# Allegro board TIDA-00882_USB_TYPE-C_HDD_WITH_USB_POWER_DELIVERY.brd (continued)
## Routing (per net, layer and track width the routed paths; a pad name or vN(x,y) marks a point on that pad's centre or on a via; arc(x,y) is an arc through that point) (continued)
GPIO7: length 4.6
  TOP w0.102: U9.D7 v1(30.73,63.62)
  TOP w0.241: R61.1 v1(33.13,65.74)
  BOTTOM w0.191: v1(30.73,63.62) 30.73,64.23 32.24,65.74 v1(33.13,65.74)
GPIO8: length 6.3
  TOP w0.102: v1(30.03,60.73) 30.23,60.93 U9.H6
  TOP w0.241: R65.1 v1(28.13,56.21)
  BOTTOM w0.191: v1(30.03,60.73) 28.13,58.83 v1(28.13,56.21)
GRST#: length 25.9
  TOP w0.191: v1(23.88,23.09) 24.79,23.09 R85.1 24.82,23.55 25.26,23.99 U13.20
  TOP w0.241: U6.4 v1(27.41,41.22)
  BOTTOM w0.191: v1(27.41,41.22) 29.57,39.06 29.57,31.14 28.18,29.74 27.45,29.74 23.88,26.18 v1(23.88,23.09)
HDD_LED#: length 15.8
  TOP w0.191: D1.1 v1(21.8,31.58)
  TOP w0.241: v1(26.6,41.22) 26.6,39.92 U6.2
  BOTTOM w0.191: v1(26.6,41.22) 24.37,41.22 22.71,39.56 22.71,38.24 21.05,36.59 21.05,32.33 v1(21.8,31.58)
HLD#: length 2.1
  TOP w0.241: R6.1 38.53,41.56 38.65,41.68 U7.7
HRESET: length 13.7
  TOP w0.102: v1(30.08,63.53) 30.23,63.37 U9.D6
  TOP w0.191: R52.1 v1(38.29,69.93)
  BOTTOM w0.191: v1(38.29,69.93) 38.29,67.62 37.54,66.87 32.51,66.87 30.11,64.47 30.11,64 30.08,63.98 v1(30.08,63.53)
HV_GATE1: length 5.9
  TOP w0.102: U8.C1 34.42,68.25 31.96,65.79 31.96,64.99 31.96,64.99 31.96,64.43 U9.B9
HV_GATE2: length 6.1
  TOP w0.102: U8.C2 34.15,69.36 34.15,68.88 34.17,68.85 34.17,68.29 31.73,65.85 U9.A9
I2C_ADDR: length 1.3
  TOP w0.102: U9.F1 27.39,62.2 27.29,62.31 R64.2
I2C_IRQ1Z: length 52.2
  TOP w0.102: U9.C1 27.29,63.7 27.08,63.5 26.37,63.5 v1(26.02,63.86)
  TOP w0.191: v1(18.73,58.39) 19.25,58.39 R91.2 ; R23.1 v1(29.09,31.6)
  BOTTOM w0.191: v1(26.02,63.86) 25.46,63.3 20.94,63.3 18.73,61.09 v1(18.73,58.39) 18.73,32.51 20.62,30.62 24.06,30.62 25.51,32.07 28.62,32.07 v1(29.09,31.6)
I2C_SCL: length 10.3
  TOP w0.191: J3.1 53.53,64.28 48.46,69.35 R50.1 R47.1
I2C_SCL1: length 84.5
  TOP w0.102: v1(28.71,63.09) 28.6,63.2 U9.D2
  TOP w0.191: R43.2 R50.2 v1(48.23,70.4) ; R22.1 v1(34.83,31.57)
  L3_SIG w0.191: v1(34.83,31.57) 34.83,34.14 42.98,42.29 42.98,48.01 41.79,49.2 39.73,49.2 34.76,54.18 25.89,54.18 24.54,55.52 v1(24.54,56.59) ; v1(48.23,70.4) 46.71,70.4 43.19,73.91 32.62,73.91 32.21,73.5 32.21,71.8 31.1,70.69 31.1,65.71 30.51,65.13 30.03,65.13 28.71,63.8 v1(28.71,63.09)
  BOTTOM w0.191: v1(24.54,56.59) 26.5,58.55 26.5,59.28 29.29,62.08 29.29,62.74 29.14,62.89 28.91,62.89 v1(28.71,63.09)
I2C_SCL2: length 27.3
  TOP w0.102: U9.B5 29.73,63.94 v1(29.6,63.83)
  TOP w0.191: R45.2 R47.2 v1(45.46,70.4)
  L3_SIG w0.191: v1(45.46,70.4) 42.42,73.44 33.08,73.44 32.65,73 32.65,71.4 31.58,70.33 31.58,65.33 30.4,64.15 29.92,64.15 v1(29.6,63.83)
I2C_SDA: length 11.1
  TOP w0.191: J3.3 56.98,64.26 56.98,61.57 56.57,61.16 52.59,61.16 51.9,61.85 R49.1 R48.1
I2C_SDA1: length 81.1
  TOP w0.102: v1(25.36,64.34) 25.64,64.06 25.64,63.7 26.13,63.2 U9.D1
  TOP w0.191: R21.1 v1(27.95,31.62) ; v1(48.2,62.45) R44.2 R49.2
  L4_PWR w0.191: v1(39.76,64.16) 39.73,64.14 39.73,63.7 39.35,63.32 37.07,63.32 35.21,65.18 33.09,65.18 32.55,64.64 30.22,64.64 29.63,65.23 29.27,65.23 29.24,65.25 26.78,65.25 26.72,65.24 26.26,65.24 v1(25.36,64.34)
  BOTTOM w0.191: v1(39.76,64.16) 42.43,64.16 43.29,63.3 47.35,63.3 v1(48.2,62.45) ; v1(27.95,31.62) 27.5,31.62 27.47,31.6 25.77,31.6 24.33,30.16 20.52,30.16 18.07,32.62 18.07,62.46 20.35,64.74 22.72,64.74 23.12,64.34 v1(25.36,64.34)
I2C_SDA2: length 30.7
  TOP w0.102: v1(29.85,65.65) 29.85,65.27 29.73,65.15 U9.A5
  TOP w0.191: v1(48.2,61.13) R46.2 R48.2
  BOTTOM w0.191: v1(29.85,65.65) 30,65.8 30,66.69 30.7,67.39 37.14,67.39 37.55,67.8 37.55,69.94 38.04,70.43 40.19,70.43 45.12,65.51 46.31,65.51 48.85,62.97 48.85,61.77 v1(48.2,61.13)
ILIM1: length 2.2
  TOP w0.191: R87.1 24.06,15.67 23.47,16.26 U14.7
JACK_DETECT: length 27
  TOP w0.191: R19.1 v1(32.52,31.65)
  TOP w0.241: U12.1 v1(40.44,49.88) 39.88,50.43 R27.1
  BOTTOM w0.191: v1(40.44,49.88) 39.89,49.33 39.89,45.14 37.52,42.77 33.87,42.77 32.27,41.17 32.27,38.91 33.42,37.76 33.42,32.55 v1(32.52,31.65)
LDO_1V8A: length 3.8
  TOP w0.102: U9.K1 27.34,60.2 25.43,58.29 C61.2
LDO_1V8D: length 2.2
  TOP w0.191: U9.A2 28.23,64.78 27.3,65.71 C58.2
LDO_3V3: length 15.1
  TOP w0.102: U9.G1 27.35,61.7 v1(27.21,61.57)
  TOP w0.191: v1(42.22,57.16) 42.21,57.18 R39.1 ; R91.1 v1(21.02,58.39) ; R44.1 v1(47.16,62.45) ; R46.1 v1(47.16,61.15)
  TOP w0.241: R45.1 v1(46.26,73.23) ; U12.6 v1(41.14,51.29) ; R43.1 v1(47.38,73.23) ; R56.2 v1(26.86,58.14) ; R36.1 v1(21.84,66.59) ; R35.1 v1(23.59,67.32) ; R57.2 v1(28.58,58.19) ; C59.2 v1(23.66,62.74)
  BOTTOM w0.191: v1(60.74,72.44) 61.23,71.95 R40.1 ; R38.1 v1(58.34,68.03) ; R41.1 v1(61.17,61.7) ; C62.2 v1(58.34,64.17) ; v1(60.76,65.86) 61.04,65.58 U10.8 ; R42.2 v1(65.74,71.42)
LDO_BMC: length 4.3
  TOP w0.102: U9.E1 25.95,62.7 24.57,64.08 C60.2
MR#: length 1.6
  TOP w0.191: U13.1 26.64,22.22 26.63,22.21 R84.2
PD_BUSPWRZ: length 12.7
  TOP w0.102: U9.F10 31.93,61.9 v1(31.76,61.9)
  TOP w0.191: R39.2 40.33,58.41 40.16,58.58 v1(40.16,59.03)
  BOTTOM w0.191: v1(40.16,59.03) 36.66,59.03 35.92,59.77 35.92,59.77 33.38,59.77 32.82,60.33 32.82,61.29 32.21,61.9 v1(31.76,61.9)
PD_MRESET: length 13.9
  TOP w0.102: U9.E11 v1(33.76,62.7)
  TOP w0.191: R37.1 v1(44.36,60.83)
  BOTTOM w0.191: v1(33.76,62.7) 34.81,63.75 36.79,63.75 37.5,63.04 40.34,63.04 42.55,60.83 v1(44.36,60.83)
PGOOD: length 20.5
  TOP w0.191: U11.3 v1(41.72,33.4) ; R79.1 v1(51.95,33.1) ; R74.2 v1(52.2,37.44)
  BOTTOM w0.191: v1(51.95,33.1) 51.95,34.32 51.37,34.9 51.37,36.6 v1(52.2,37.44) 49.16,37.44 46.87,35.15 43.85,35.15 43.49,34.8 43.49,33.99 42.91,33.4 v1(41.72,33.4)
PMIC_5V: length 8.6
  TOP w0.191: v1(30.06,25.07) 29.78,24.79 U13.8 ; U13.3 27.44,22.83 v1(27.69,22.58) 27.84,22.73 U13.4 ; U13.18 25.41,24.79 v1(25.18,24.56) 25.35,24.39 U13.19 ; U14.9 23.47,17.26 24.2,18 C78.1 v1(24.2,19.24) ; R84.1 v1(25.88,20.66) ; U13.10 v1(28.94,26.01)
  vias: v1(25.74,26.97) v1(26.25,26.97)
POL: length 12.3
  TOP w0.191: R26.1 42.78,57.76 v1(42.78,57.53) ; U1.9 47.88,53.65 v1(46.68,52.45)
  L3_SIG w0.191: v1(47.15,56.21) 47.15,53.92 46.68,53.45 v1(46.68,52.45)
  L4_PWR w0.191: v1(47.15,56.21) 46.6,56.76 43.21,56.76 42.86,57.12 42.86,57.46 v1(42.78,57.53)
R_OSC: length 8.1
  TOP w0.102: U9.G2 27.95,61.99 26.77,61.99 26.62,61.84 25.39,61.84 25.08,62.15 25.08,63.17 24.84,63.41 R32.1
REF1: length 0.6
  TOP w0.241: U12.5 U12.4
RF: length 7.9
  TOP w0.191: R77.2 48,35.12 v1(47.97,35.09) U11.22 ; R73.2 v1(51.9,30.84)
  BOTTOM w0.191: v1(47.97,35.09) 48.29,34.77 48.29,34.44 v1(51.9,30.84)
SATA_5V:
  vias: v1(30.23,3.3) v1(30.23,2.67) v1(30.87,3.3) v1(30.87,2.67) v1(31.5,3.3) v1(31.5,2.67)
SATA_EN: length 40.1
  TOP w0.191: R86.1 R83.1 18.68,15.1 18.68,15.42 19.02,15.76 U14.5 v1(19.84,15.11)
  TOP w0.241: U6.22 v1(32.16,43.11)
  BOTTOM w0.191: v1(19.84,15.11) 19.84,17.65 20.61,18.41 20.61,20.95 21.52,21.87 24.11,21.87 26.22,23.98 26.22,24.71 29.26,27.75 29.26,30.11 31.53,32.38 31.53,37.87 30.95,38.46 30.95,42.42 31.63,43.11 v1(32.16,43.11)
SATARXM: length 46.1
  TOP w0.127: C12.2 12.53,4.67 12.6,4.75 12.6,6.63 13.66,7.69 13.66,35.32 21.4,43.05 21.64,43.05 23.88,43.05 23.93,43.11 U6.59
SATARXP: length 46.1
  TOP w0.127: C13.2 13.34,4.23 12.9,4.67 12.9,6.52 13.96,7.57 13.96,35.2 21.52,42.76 24.15,42.76 24.2,42.71 U6.60
SATATXM: length 49.3
  TOP w0.127: U6.56 24.22,44.31 24.17,44.25 20.77,44.25 12.49,35.98 12.49,10.26 8.81,6.57 8.81,4.76 8.72,4.67 C11.2
SATATXP: length 49.3
  TOP w0.127: C14.2 9.5,4.23 9.1,4.62 9.1,6.45 12.79,10.14 12.79,35.86 20.89,43.96 23.88,43.96 23.93,43.91 U6.57
SPI_CE#: length 14.5
  TOP w0.241: U6.21 34.95,42.71 35.72,41.94 35.72,40.31 36.99,39.04 38.13,39.04 38.62,39.52 42.48,39.52 43.37,40.41 U7.1
SPI_CLK: length 68.7
  TOP w0.102: U9.A3 28.73,65.05 28.19,65.59 v1(28.19,65.76)
  TOP w0.191: J3.7 v1(62.03,61.47)
  BOTTOM w0.191: 63.58,61.95 63.61,61.93 66.2,61.93 67.37,63.09 67.37,71.73 65.21,73.89 60.89,73.89 59.22,72.21 37.38,72.21 36.46,73.13 33.25,73.13 32.78,72.66 32.78,72.06 31.76,71.05 29.54,71.05 27.44,68.94 27.44,67.96 27.09,67.62 27.09,66.86 v1(28.19,65.76) ; 63.58,61.95 63.1,61.47 v1(62.03,61.47) ; 63.58,61.95 U10.6
SPI_HOLD#: length 2
  BOTTOM w0.191: U10.7 62.2,64.04 R41.2
SPI_MISO: length 47.6
  TOP w0.102: U9.A4 29.23,65.21 29.23,65.5 v1(28.96,65.77)
  TOP w0.191: J3.5 v1(59.49,67.18)
  BOTTOM w0.191: R40.2 62.28,70.64 62.31,70.61 U10.2 62.29,69.01 62.29,67.84 61.63,67.18 v1(59.49,67.18) 54.77,67.18 50.63,71.32 37.25,71.32 36.29,70.36 32.5,70.36 32.08,69.94 29.69,69.94 28.6,68.85 28.6,67.01 28.96,66.65 v1(28.96,65.77)
SPI_MOSI: length 58.5
  TOP w0.102: v1(29.45,66.16) 29.45,64.95 29.48,64.92 29.48,64.45 U9.B4
  TOP w0.191: J3.8 v1(62.03,73.08)
  BOTTOM w0.191: 64.85,66.12 64.85,66.55 66.38,68.07 66.38,71.55 65.57,72.36 63.71,72.36 63,73.08 v1(62.03,73.08) ; 64.85,66.12 U10.5 ; 64.85,66.12 63.3,66.12 62.85,66.57 54.06,66.57 49.77,70.87 37.54,70.87 36.58,69.91 32.83,69.91 32.41,69.49 30.48,69.49 29.99,69 29.45,68.46 v1(29.45,66.16)
SPI_SCK: length 11.3
  TOP w0.241: v1(41.59,42.93) 40.01,42.93 U7.6 ; U6.17 v1(33.41,40.56)
  BOTTOM w0.191: v1(41.59,42.93) 39.22,40.56 v1(33.41,40.56)
SPI_SI: length 10.8
  TOP w0.241: v1(41.56,44.22) U7.5 ; U6.18 v1(34.66,41.51)
  BOTTOM w0.191: v1(34.66,41.51) 38.85,41.51 v1(41.56,44.22)
SPI_SO: length 18
  TOP w0.241: U6.20 34.64,42.31 v1(34.76,42.19) ; v1(47.82,40.96) 47.83,40.96 R11.1
  BOTTOM w0.191: v1(34.76,42.19) 38.23,42.19 41.05,45.01 43.77,45.01 v1(47.82,40.96)
SPI_SO_J: length 1.9
  TOP w0.241: R11.2 46.28,41.65 46.28,41.66 46.25,41.68 U7.2
SPI_SSZ: length 52.1
  TOP w0.102: v1(28.31,66.35) 28.57,66.09 28.57,65.53 28.99,65.11 28.99,64.46 U9.B3
  TOP w0.191: J3.9 64.57,66.02 63.37,67.23 61.4,67.23 60.84,67.79 v1(60.84,70.59)
  BOTTOM w0.191: v1(28.31,66.35) 28.05,66.61 28.05,68.9 29.63,70.48 31.81,70.48 32.2,70.88 36.07,70.88 36.95,71.75 55.02,71.75 56.19,70.59 v1(60.84,70.59) 60.84,69.24 U10.1 59.91,69.04 59.87,69.08 R38.2
SPI_WP#: length 2.4
  BOTTOM w0.191: R42.1 63.62,70.64 63.58,70.61 U10.3
SS: length 4.4
  TOP w0.241: C51.2 v1(33.61,59.13) ; U9.H7 v1(30.73,60.89)
  BOTTOM w0.191: v1(33.61,59.13) 32.49,59.13 v1(30.73,60.89)
SS_MUX_EN#: length 79.4
  TOP w0.191: v1(44.76,73.2) 44.76,70.23 45.65,69.34 45.65,64.87 43.06,62.28 43.06,58.51 43.57,58 44.51,58.94 R3.1 ; R20.1 v1(33.69,31.62)
  TOP w0.241: 43.57,58 v1(43.57,57.41) ; R25.1 v1(25.56,67.89)
  L3_SIG w0.191: v1(33.69,31.62) 34.42,30.89 39.07,30.89 40.22,32.03 40.22,36.6 44.48,40.87 44.48,52.65 43,54.14 43,56.83 v1(43.57,57.41)
  BOTTOM w0.191: v1(25.56,67.89) 25.56,68.96 28.18,71.58 31.71,71.58 32.22,72.09 32.22,72.83 33.1,73.71 44.25,73.71 v1(44.76,73.2)
TLV_INP: length 3.1
  TOP w0.241: U12.3 42.44,49.17 42.67,48.94 R71.2 R66.1
TRIP: length 4
  TOP w0.191: U11.21 48.52,33.9 48.85,34.24 48.85,35.98 R75.2
TRST: length 1.9
  TOP w0.191: C80.1 27.04,22.49 U13.2
TYPEC_VBUS: length 10.6
  TOP w0.191: J1.B4 68.47,57.51 v1(68.85,57.9) ; J1.A4 v1(65.88,55.01) J1.B9 v1(68.44,55.01)
  TOP w0.241: J1.B4 v1(65.87,57.51) J1.A9
  BOTTOM w0.241: v1(68.85,57.9) 68.95,58 C1.2 ; C3.2 68.47,54.98 v1(68.44,55.01) ; v1(65.87,57.51) 65.47,57.91 C2.2 ; v1(65.88,55.01) 66.33,55.01 C5.2
  vias: v1(38.79,60.48) v1(38.79,59.97) v1(39.35,60.45) v1(39.35,59.94)
UART_RX: length 94.3
  TOP w0.191: U6.5 27.81,38.79 v1(27.6,38.59) ; v1(19.99,32.48) v1(16.78,32.48)
  BOTTOM w0.191: v1(27.6,38.59) 27.6,35.37 27.93,35.04 27.93,33.47 26.98,32.52 25.29,32.52 23.91,31.14 20.77,31.14 19.99,31.92 v1(19.99,32.48) ; v1(16.78,32.48) 14.79,30.46 14.79,14.7 20.28,9.22 52.23,9.22 54.59,6.86 64.96,6.86 J2.3
UART_TX: length 82.7
  TOP w0.191: v1(20.53,27.79) 20.53,32.79 21.17,33.42 25.86,33.42 26.68,34.24 26.68,37.52 27.11,37.95 27.57,37.95 28.21,38.59 U6.6
  BOTTOM w0.191: v1(20.53,27.79) 16.8,24.05 16.8,15.09 21.55,10.34 62.7,10.34 J2.2
UART_TX_RX: length 7.7
  TOP w0.102: U9.F2 U9.E2 27.95,62.99 26.02,62.99 24.21,64.8 R51.1
USB3_RX0N: length 28.2
  TOP w0.14: U6.45 27.41,49.1 27.34,49.17 27.34,53.57 28.84,55.07 34.2,55.07 34.98,54.28 40.7,54.28 43.1,56.67 46.36,56.67 46.44,56.6 46.44,56.45 46.52,56.38 46.63,56.38 46.71,56.45 46.71,56.6 46.79,56.67 47.76,56.67 U1.4
USB3_RX0P: length 28.2
  TOP w0.14: U6.46 27.01,49.1 27.08,49.17 27.08,53.67 28.73,55.32 34.3,55.32 35.09,54.53 40.6,54.53 42.99,56.93 47.76,56.93 U1.3
USB3_TX0N: length 25.9
  TOP w0.14: U6.42 28.61,49.17 28.54,49.25 28.54,53.04 29.4,53.9 33.46,53.9 34.27,53.09 45.56,53.09 46.66,54.19 46.77,54.19 46.87,54.08 46.98,54.08 47.06,54.16 47.06,54.27 46.96,54.37 46.96,54.49 47.15,54.67 47.76,54.67 U1.8
USB3_TX0P: length 25.9
  TOP w0.14: U6.43 28.21,49.16 28.28,49.23 28.28,53.14 29.29,54.15 33.57,54.15 34.38,53.34 45.45,53.34 47.04,54.93 47.76,54.93 U1.7
USB_R1: length 5.3
  TOP w0.191: v1(30.42,49.66) 30.21,49.45 U6.38
  TOP w0.241: R9.1 v1(30.98,52.41)
  BOTTOM w0.191: v1(30.98,52.41) 30.97,52.48 30.97,51.94 30.42,51.39 v1(30.42,49.66)
USB_R1RTN: length 5.1
  TOP w0.191: U6.39 v1(29.81,49.67)
  TOP w0.241: R9.2 v1(29.84,52.44)
  BOTTOM w0.191: v1(29.84,52.44) 29.81,52.6 v1(29.81,49.67)
USB_RP_N: length 14.5
  TOP w0.102: 29.57,58.85 29.57,59.16 29.98,59.56 29.98,59.96 U9.K5
  TOP w0.14: v1(32.35,53.26) 32.23,53.13 32.23,50.94 31.34,50.06 31.34,49.19 31.41,49.12 U6.35 ; 29.57,58.85 29.57,58.85 29.57,58.39 29.3,58.12 29.3,57.64 29.57,57.37 29.57,56.64 29.71,56.5 v1(29.71,56.44)
  BOTTOM w0.14: v1(29.71,56.44) 29.58,56.3 29.58,55.72 30.69,54.61 31.38,54.61 32.22,53.77 32.22,53.4 v1(32.35,53.26)
USB_RP_P: length 14.5
  TOP w0.102: U9.L5 29.73,59.63 29.32,59.22 29.32,58.83
  TOP w0.14: 29.32,58.83 29.32,58.5 29.05,58.23 29.05,57.53 29.32,57.26 29.32,56.58 v1(29.18,56.44) ; v1(31.82,53.26) 31.97,53.11 31.97,51.05 31.57,50.65 31.46,50.65 31.3,50.81 31.19,50.81 31.11,50.74 31.11,50.62 31.27,50.46 31.27,50.35 31.08,50.16 31.08,49.2 31.01,49.13 U6.36
  BOTTOM w0.14: v1(29.18,56.44) 29.33,56.29 29.33,55.62 30.59,54.36 31.27,54.36 31.96,53.67 31.96,53.4 v1(31.82,53.26)
USB_VBUS: length 10.6
  TOP w0.241: U6.50 v1(26.25,46.71) ; v1(21.09,50.75) R13.1 ; R16.2 v1(22.23,50.75)
  BOTTOM w0.191: v1(22.23,50.75) 22.23,49.12 24.65,46.71 v1(26.25,46.71)
  BOTTOM w0.241: v1(22.23,50.75) v1(21.09,50.75)
VBST: length 1.4
  TOP w0.191: R70.1 42.04,32.9 U11.4
VFB: length 4.2
  TOP w0.191: U11.1 43.02,35.39 43.02,35.39 R76.1 R69.2
  TOP w0.241: R69.2 C70.1
VFB_C: length 2.3
  TOP w0.191: R68.2 39.28,34.23 39.29,34.25 C69.1 C70.2
VREG: length 4.6
  TOP w0.191: U11.18 49.62,32.4 49.64,32.38 49.73,32.38 C72.1 ; C72.1 R73.1 ; C72.1 50.16,32.46 50.19,32.48 R79.2
WP#: length 4.5
  TOP w0.191: R8.1 43.01,43.53
  TOP w0.241: 43.01,43.53 43.59,42.95 U7.3
XI: length 11.8
  TOP w0.191: C20.1 17.43,49.54 17.97,49 ; U6.52 23.8,45.91 23.1,46.61 23.1,47.69 21.98,48.8 X1.3 21.78,48.8 20.65,49.94 18.7,49.94 17.97,49.2 17.97,49 ; 17.97,49 R12.2
XO: length 9.7
  TOP w0.191: C19.1 17.38,47.03 17.54,47.03 R12.1 19.13,47.46 X1.1 20.38,46.21 21.9,46.21 23,45.11 U6.54
N17726709: length 3.2
  TOP w0.191: R17.2 24.16,31.08 23.36,31.88 D1.2
N17832078: length 11.8
  TOP w0.191: U11.19 48.81,32.9 50.5,34.59 C82.1 50.68,34.72 51.75,33.66 52.56,33.66 53.07,33.15 53.07,30.25 52.48,29.67 R89.1
N17839350: length 1.1
  TOP w0.191: R70.2 C66.2
N17883338: length 1.4
  TOP w0.241: R88.1 48.44,20.52 48.41,20.55 48.08,20.55 48.08,20.54 D3.1

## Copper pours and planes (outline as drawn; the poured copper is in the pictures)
GND on TOP: 29.09,61.06 29.83,61.06 29.88,61.11 29.88,61.47 29.98,61.57 31.02,61.57 31.1,61.49 31.1,61.11 31.15,61.06 31.35,61.06 31.38,61.09 31.38,63.27 31.3,63.35 31.15,63.35 31.1,63.3 31.1,62.92 31.02,62.84 29.62,62.84 29.57,62.79 29.57,61.44 29.47,61.34 29.09,61.34
GND on TOP: 28.02,11.81 30.95,11.81 33.89,14.76 39.91,14.76 39.91,19.58 39.78,19.71 31.63,19.71 28.02,16.1
GND on TOP: 35.85,70.76 36.84,70.76 37.27,71.2 38.69,71.2 39.53,70.36 43.59,70.36 43.62,70.38 43.62,73.36 43.49,73.48 35.97,73.48 35.85,73.36
GND on TOP: 43.87,34.67 43.87,29.18 44.86,28.19 45.63,28.19 45.63,23.57 49,23.57 49,26.26 48.98,26.29 47.66,26.29 46.95,27 46.95,28.93 47.12,29.11 47.12,34.67
GND on TOP: 40.6,66.42 40.6,63.86 43.95,63.86 43.95,66.42
GND on TOP: 28.1,74.23 28.1,71.7 22.66,71.7 22.66,74.23
GND on TOP: 51.01,6.27 51.01,0.86 61.25,0.86 61.25,6.27
GND on L2_GND: 70.24,0.51 0.52,0.51 0.54,13.94 9.95,23.33 9.95,37.24 13.39,40.67 13.39,50.87 15.98,53.47 15.98,74.24 70.21,74.24 70.24,48.26 56.85,48.26 53.86,45.27 53.86,23.5 70.24,23.5
GND on L5_GND: 70.24,0.51 0.52,0.51 0.54,13.94 9.92,23.29 9.92,37.2 13.39,40.67 13.39,50.87 15.98,53.47 15.98,74.24 70.21,74.24 70.24,48.26 56.85,48.26 53.86,45.27 53.86,23.5 70.24,23.5
VDD_1P1V on L3_SIG: 30.18,37.21 31.88,37.21 34.04,39.37 34.04,41.12 34.03,41.13 34.03,43.72 33.53,44.22 33.53,45.72 34.91,47.09 36.86,49.05 36.86,50.65 24.52,50.65 24.52,43.69 21.29,40.46 21.29,38.74 26.23,38.74 26.96,39.47 29.52,39.47 30.06,38.94 30.06,37.34
VDD_3P3V on L3_SIG: outline of 126 points within 0.76,0.61 42.16,54.12 ; 1 cut-out
VDDA_3P3V on BOTTOM: 26.07,41.68 25.92,41.83 25.92,42.8 26.83,43.71 26.83,47.65 23.45,51.03 23.45,51.33 23.63,51.51 24.82,51.51 28.66,47.68 29.73,47.68 31.17,49.12 31.17,49.83 31.5,50.16 32.06,50.16 32.27,49.96 32.27,49.07 29.9,46.71 27.47,46.71 27.47,42.57 26.58,41.68
53318_LL on TOP: 43.44,32.05 42.35,32.05 42.07,31.78 41.51,31.78 41.51,31 40.1,31 39.53,31.57 39.53,32.84 39.5,32.87 38.74,32.87 37.37,31.5 37.37,26.59 40.32,26.59 42.18,28.46 43.47,28.46 43.47,32.03
65982_5V on TOP: 34.45,62.15 34.45,63.07 32.6,63.07 32.57,63.09 32.57,64.85 32.6,64.87 34.45,64.87 34.45,67.46 35.21,67.46 35.21,64.87 35.31,64.87 35.47,64.72 35.47,63.3 35.24,63.07 35.21,63.07 35.21,62.15
65982_5V on L3_SIG: 31.55,61.44 32.14,61.44 32.32,61.62 32.32,64.71 33.75,64.71 33.84,64.62 33.84,63.75 33.71,63.63 32.8,63.63 32.77,63.6 32.77,60.91 31.53,60.91 31.5,60.93 31.5,61.39
65982_VBUS on TOP: 32.57,61.32 32.57,60.96 32.44,60.83 32.14,60.83 32.06,60.76 32.06,60.63 32.14,60.55 32.44,60.55 32.57,60.43 32.57,60.12 32.6,60.1 33.1,60.1 33.63,59.57 36.3,59.57 36.3,61.34 32.6,61.34
65982_VBUS on TOP: 32.98,69.49 33.87,69.49 33.97,69.6 33.97,70.08 33.99,70.1 34.93,70.1 34.93,69.57 35.01,69.49 35.85,69.49 35.9,69.55 35.9,70.03 35.06,70.87 35.06,72.82 32.98,72.82
65982_VBUS on L3_SIG: 35.94,59.92 35.94,61.4 40.89,66.36 40.89,72.34 37.57,72.34 37.09,72.82 35.09,72.82 33.08,72.82 33.08,69.75 37.02,69.75 37.34,69.43 37.34,67.87 34.36,64.89 34.13,64.89 34.13,63.41 33.26,63.41 33.26,59.92
87501_S1 on TOP: 38.74,69.48 38.74,68.47 36.16,68.47 36.16,69.48
87501_S1 on BOTTOM: 37.17,68.39 37.17,69.4 32.83,69.4 32.83,68.39
87501_S1 on L3_SIG: 32.09,64.95 32.93,64.95 35.96,67.98 35.96,68.71 35.73,68.94 32.79,68.94 32.61,68.76 32.61,68.29 32.07,67.76 32.07,64.97
BOARD_1P1V on TOP: 34.3,25.63 34.3,27.43 32.57,27.43 31.86,28.14 31.86,31.17 29.34,31.17 29.34,28.45 29.5,28.3 30.13,28.3 30.34,28.09 30.34,25.63
BOARD_1P1V on L4_PWR: 30.26,26.95 30.26,56.92 36.65,56.92 36.65,51.46 38.9,49.22 38.9,45.97 32.65,39.72 32.65,26.77 30.44,26.77
BOARD_1P8V on TOP: 26.35,25.1 26.35,26.19 24.14,26.19 24.14,25.1
BOARD_3P3V on TOP: 27.54,25.91 27.54,26.77 28.15,27.38 28.15,28.37 26.75,28.37 26.75,27.58 26.93,27.41 26.93,25.91
BOARD_3P3V on TOP: 21.06,6.73 21.06,2.26 22.99,2.26 22.99,6.73
BOARD_3P3V on TOP: 48.19,55.7 46.77,55.7 46.16,56.31 45.09,56.31 45.07,56.29 45.07,54.61 46.11,54.61 46.9,55.4 48.19,55.4
BOARD_3P3V on BOTTOM: 21.01,0.64 21.01,3.51 22.97,3.51 22.97,0.64
BOARD_3P3V on L4_PWR: 0.65,0.59 0.65,10.45 41.11,10.45 45.22,14.56 45.22,23.93 40.24,28.91 40.24,34.9 38.92,36.22 37.19,36.22 35.77,34.8 35.77,24.12 35.14,23.5 24.49,23.5 22.89,25.1 22.89,32.43 27.45,35.63 22.89,38.82 22.89,53.37 22.59,53.67 22.58,59.38 22.59,59.38 22.59,60.4 29.14,60.4 29.14,59.4 29.12,59.38 29.12,51.18 29.09,51.18 29.09,26.08 33.64,26.08 33.64,39.61 37.45,43.42 37.45,43.41 39.84,45.8 39.84,56.33 46.26,56.33 46.26,54.69 45.02,54.69 41.54,51.21 41.54,46.18 42.55,45.16 42.55,40.61 42.31,40.37 42.31,36.23 47.26,31.29 47.26,28.34 44.43,31.17 44.43,31.11 49.06,26.49 49.06,0.59
BOARD_5V on TOP: 36.43,63.35 36.43,65 38.92,65 38.92,63.35
BOARD_5V on TOP: 18.04,16.13 18.04,17.37 18.02,17.37 18.02,18.97 19.06,18.97 19.06,17.42 20.25,17.42 20.25,16.13
BOARD_5V on TOP: 30.11,70.69 30.11,74.23 28.79,74.23 28.79,70.69
BOARD_5V on TOP: 43.87,28.17 42.32,28.17 40.34,26.19 38.44,26.19 37.37,25.12 37.37,21.79 37.42,21.74 43.87,21.74
BOARD_5V on L4_PWR: 0.77,11.79 0.77,14.57 9.95,23.74 9.95,37.18 10.43,37.66 10.44,37.66 13.44,40.66 13.44,50.84 16.04,53.43 16.04,74.05 16.08,74.09 30.06,74.09 30.06,70.92 31.94,69.04 39.25,69.04 39.25,63.86 37.75,63.86 35.52,66.09 25.69,66.09 21.55,61.95 21.55,37.99 20.61,35.63 21.55,33.26 21.55,24.41 23.96,22 35.06,22 36.74,23.67 36.74,34.32 37.71,35.29 38.65,35.29 39.49,34.44 39.49,27.85 44.15,23.19 44.15,15.49 40.44,11.79 ; 1 cut-out
BOARD_12V on TOP: 37.37,65.97 39.33,65.97 40.19,66.83 45.14,66.83 45.14,69.13 45.14,69.13 44.49,69.78 40.68,69.78 38.87,67.97 37.88,67.97 37.37,67.46
BOARD_12V on TOP: 30.82,70.69 30.82,74.23 32.14,74.23 32.14,70.69
BOARD_12V on TOP: 51.06,9.65 47.63,13.08 47.63,16.92 53.12,16.92 54.29,18.08 54.29,22.15 55.61,23.47 62.72,23.47 62.72,20.04 59.16,20.04 58.43,19.3 58.43,9.98 58.1,9.65
BOARD_12V on TOP: 47.56,32.03 47.56,27.33 47.66,27.23 49.54,27.23 49.72,27.05 50.25,27.05 50.25,29.92 50.07,29.92 49.33,30.66 49.33,32.05 47.58,32.05
BOARD_12V on L4_PWR: 30.84,74.12 30.84,71.37 32.47,69.75 40.37,69.75 40.37,62.66 35.04,62.66 33.61,64.09 30.16,64.09 30.16,58.11 34.14,58.11 36.26,60.23 37.31,60.23 39.44,58.11 47.86,58.11 47.86,54.25 45.37,54.25 42.1,50.98 42.1,46.71 43.44,45.36 43.44,39.37 42.98,38.91 42.98,37.11 47.99,32.11 47.99,29.06 50.22,26.82 50.22,0.72 70.18,0.72 70.18,23.47 53.83,23.47 53.83,45.34 56.89,48.4 56.92,48.38 70.18,48.38 70.18,51.08 57.36,51.08 56.16,52.29 56.16,58.75 58.95,61.55 70.18,61.55 70.11,61.62 70.11,74.12
FUSE_12V on TOP: 37.63,2.21 37.63,5.77 37.14,6.25 37.14,11.07 37.9,11.84 42.91,11.84 44.1,13.03 44.1,16.84 44.15,16.89 46.11,16.89 46.11,9.75 39.53,3.17 39.53,2.16 37.68,2.16
FUSE_12V on BOTTOM: 37.57,0.64 37.57,3.48 39.53,3.48 39.53,0.64
LDO_3V3 on L3_SIG: 27.89,73.87 16.19,73.87 16.19,55.14 22.72,55.14 22.72,55.91 24.02,57.21 24.88,57.21 26.95,55.14 39.02,55.14 40.5,53.67 40.5,51.41 40.99,50.92 41.41,50.92 42.56,52.07 42.56,57.57 38.8,57.57 37.52,58.71 37.52,60.92 39.47,62.87 44.61,62.87 46.97,60.5 47.37,60.5 50.18,63.32 58.83,63.32 60.71,61.43 61.69,61.43 63.79,63.53 70.17,63.53 70.18,63.54 70.18,74.07 70.13,74.12 46.8,74.12 45.73,73.05 45.73,72.52 46.34,71.91 48.52,71.91 49.28,71.15 49.28,69.9 48.47,69.09 44.27,69.09 36.5,61.31 36.5,59.11 30.67,59.11 27.89,61.88
PMIC_5V on TOP: 26.75,25.88 26.75,27 26.25,27.51 26.25,28.32 25.41,28.32 25.41,26.87 25.66,26.62 26.25,26.62 26.53,26.34 26.53,25.88
PMIC_5V on L3_SIG: 24.8,27.33 24.8,24.13 25.69,23.24 25.69,21.29 23.96,19.56 23.96,0.61 69.71,0.61 69.87,0.76 69.87,22.95 69.82,22.9 53.32,22.9 53.32,27.74 25.2,27.74
PP_HV on TOP: 30.59,64.06 30.59,64.44 30.49,64.54 30.21,64.54 30.13,64.62 30.13,64.9 30.17,64.94 30.17,66.08 29.19,67.06 29.19,68 28.61,68 28.02,68.58 23.96,68.58 23.91,68.63 23.91,70.05 28.3,70.05 28.66,69.7 32.14,69.7 32.19,69.65 32.19,68.4 31.48,67.7 31.48,64.75 31.28,64.54 30.97,64.54 30.87,64.44 30.87,64.06
SATA_5V on TOP: 29.93,2.39 29.93,5.64 29.45,6.12 25.97,6.12 24.75,7.34 24.75,15.75 23.88,16.61 22.36,16.61 22.36,16.87 22.39,16.89 23.81,16.89 24.47,17.55 25.36,17.55 25.38,17.53 25.38,16.26 25.79,16.26 25.79,11.3 27.29,9.8 31.81,9.8 31.86,9.75 31.86,2.39
SATA_5V on BOTTOM: 29.9,0.64 29.9,3.51 31.86,3.51 31.86,0.64
SW_1P1V on TOP: 28.53,24.28 29.5,24.28 31.07,22.71 33.59,22.71 34.35,23.47 34.35,24.41 34.25,24.51 28.53,24.51
TYPEC_VBUS on TOP: 37.22,60.05 37.63,59.64 42.32,59.64 42.32,62.38 40.27,62.38 39.2,61.32 37.24,61.32 37.22,61.29
TYPEC_VBUS on L3_SIG: 44.27,62.34 39.54,62.34 38.21,61.01 38.21,59.3 39.41,58.1 43.77,58.1 45.23,56.64 47.51,56.64 48.18,55.97 48.17,55.96 48.17,53.12 45.07,50.02 45.07,40.19 45.06,40.19 45.06,39.21 41.33,35.47 41.33,28.99 41.46,28.85 53.63,28.85 53.63,45.13 53.63,45.11 56.81,48.29 68.31,48.29 68.31,48.28 70.21,48.27 70.21,53.87 70.21,53.87 70.21,62.55 63.88,62.55 62.21,60.87 60.44,60.87 58.78,62.53 50.44,62.53 47.74,59.82 46.79,59.82

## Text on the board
BOTTOM: LAYER 4 - BOTTOM SIDE
Board Geometry/Soldermask Bottom: SOLDERMASK BOTTOM
Package Geometry/Pastemask Bottom: PASTEMASK BOTTOM
Ref Des/Silkscreen Bottom: FOR EVALUATION ONLY: | NOT FCC APPROVED FOR RESALE | SILKSCREEN BOTTOM
TOP: LAYER 1 - TOP SIDE
Board Geometry/Soldermask Top: SOLDERMASK TOP
Package Geometry/Pastemask Top: PASTEMASK TOP
Ref Des/Silkscreen Top: ACT | HDD | 3.3V PWR | * | SPI/I2C | TIDA-00882 | REV A | +12VDC | GND | TX | RX | UART | SILKSCREEN TOP
L2_GND: LAYER 2 - GND PLANE
L3_SIG: LAYER 3 - PWR PLANE
XSECTION_CHART: * AIR 0 MIL | * SOLDERMASK-0.8MIL 0.8 MIL | L1: COPPER_1/2OZ_PLATED 1.4 MIL | * FILL_0.125 4.92 MIL | L2: COPPER_1.0OZ 1.4 MIL | * FILL_0.150 5.91 MIL | L3: COPPER_1.0OZ 1.4 MIL | * CORE_0.750 29.53 MIL | L4: COPPER_1.0OZ 1.4 MIL | L5: COPPER_1.0OZ 1.4 MIL | L6: COPPER_1/2OZ_PLATED 1.4 MIL | DESIGN CROSS SECTION CHART | ___________________________ | TOTAL THICKNESS 61.19 MIL | 1-6
PAGE_OUTLINE: WITH POWER DELIVERY
DIMENSION: FABRICATION DRAWING | CAD ORIGIN
User.6: LAYER 1 | LAYER 2 | LAYER 3 | LAYER 4 | LAYER 5 | LAYER 6 | LAYER | NO. | TABLE 1: | TOP | L2_GND | L3_SIG | L2_PWR | L3_GND | BOTTOM | NAME | DIFFIRENTIAL PAIR | IMPEDANCE (OHMS) | 100 +/- 10% | 90  +/- 10% | DIFF TRACE | WIDTH | 0.005" | 0.0055" | SPACING | 0.0065" | 0.0045" | SINGLE ENDED | 50 +/- 10% | TRACE WIDTH | 0.0075" | REFERENCE | SPECIAL FAB NOTES: | PLACE DRILL CHART HERE: | 1:FAB SHOP MUST FOLLOW THE SOLDER MASK REVIEW LAYERS. | 2: | MIN. ANNULAR RING 2 MIL EXTERNAL PER IPC-6012C CLASS 2 | REGISTRATION TOLERANCES: METAL +/- X MIL,HOLES +/- X MIL | IMPEDANCE CONTROL: | BOARD SIZE (REFER ALSO ARRAY/PANEL PROFILING INFORMATION) | MIXED DIELECTRIC: | LAMINATE MATERIAL: | THICKNESS: | TOLERANCE: | COPPER THICKNESS (FINISHED): | BOARD FINISH: | NUMBER OF LAYERS: | MIN. TRACK WIDTH: | MIN. CLEARANCE  : | MIN. VIA PAD/DRILL: | THIEVING ALLOWED: | X | OUTER: | INNER SIGNAL: | INNER PLANE: | OTHER: | SILKSCREEN: | SOLDERMASK: (PER IPC-6011,6012) | BOARD SURFACE TREATMENT: | ADDITIONAL REQUIREMENTS: | VENDOR MARKING: | SILKSCREEN COLOR: | SOLDERMASK COLOR: | THROUGH-HOLE VIA TREATMENT: | VIA FILL USING NON-CONDUCTIVE EPOXY: | FOR WIRE BONDING: | VENDOR DATE CODE,UL,LOGO: | FR-4 HIGH Tg | 0.062" +/-10% | IPC-6012C TYPE 3 CLASS 2 | OTHER +/- | MICRO-SECTION | CERTIFICATES OF COMPLIANCE | NICKEL/GOLD (ENIG) | IMMERSION TIN | HARD GOLD | IN AN OPEN AREA | 1/4 OZ. | OPEN | NO | 6 | 4.0 MIL | 4.5 MIL | 16/08 MIL | NONE | DESIGN INFORMATION | ROGERS 4350B | 0.093" +/-10% | YES | TDR REPORTS/COUPONS | WHITE | GREEN | SOFT GOLD | TENTED | 1/2 OZ. | BOW & TWIST: | ORGANIC (OSP) | OTHER | WHERE INDICATED (SEE DRAWING) | YES - SEE TABLE 1 | ETCH | IDENTIFIER: | BLUE | RoHS | 1.0 OZ. | SILKSCREEN | PER SUPPLIED ARTWORK | ALL x MIL VIAS | ELECTRICAL TEST | UL 94V-0 | HASL | 2.0 OZ. | BREAK-AWAY | ENEPIG
User.10: FIGURE | SIZE | 150.0 | 71.0 | 38.0 | 17.72 | 8.0 | 100.0 | 70.0 | 47.24 | 35.43 | 27.56 | 72.83x27.56 | 59.06x19.69 | 51.18x27.56 | 29.53x19.69 | 39.37x23.62 | DRILL CHART: TOP to BOTTOM | ALL UNITS ARE IN MILS | TOLERANCE | +3.0/-3.0 | +3.15/-3.15 | +3.0/-8.0 | +2.0/-2.0 | +1.97/-0.0 | +3.0/-3.94 | PLATED | NON-PLATED | QTY | 1 | 5 | 3 | 2 | 592
